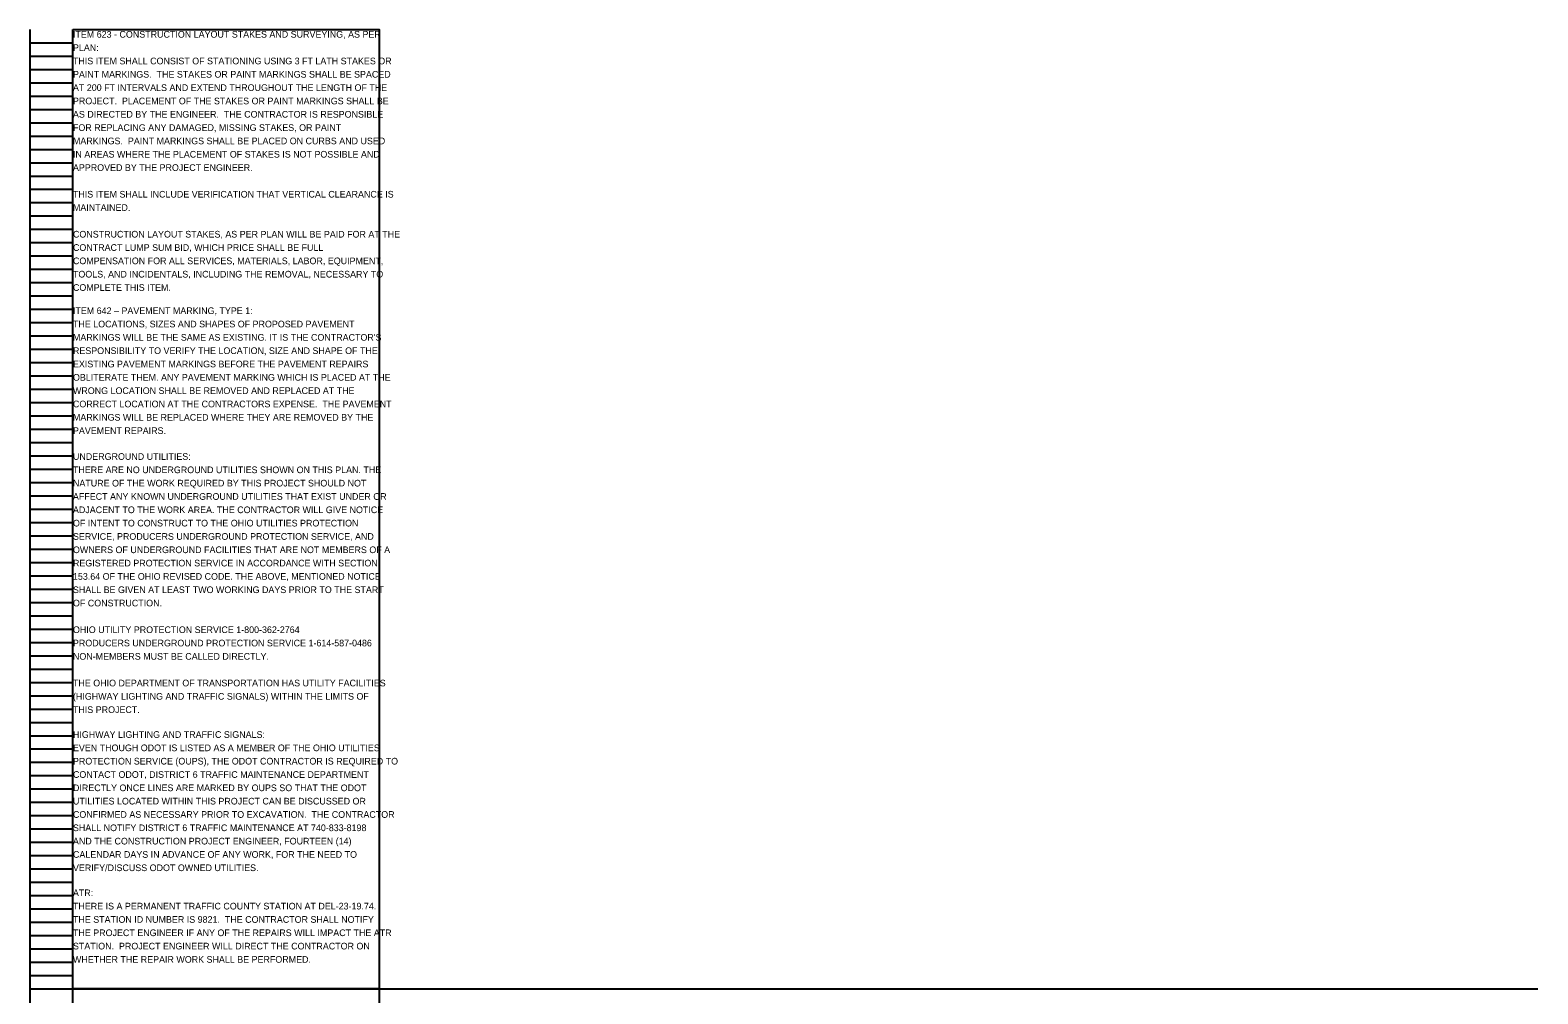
# Model space of a CAD drawing. Extents: x 16463 to 16495, y 5662 to 5823.
# Drawn here: x 16463.05 to 16494.74, y 5742.73 to 5762.98 of the extents above; entities that cross this region are included whole.
import ezdxf

# ---------------------------------------------------------------- set-up
doc = ezdxf.new("R2010")
doc.units = 0
for name, color, linetype in [('Default', 7, 'Continuous'), ('SC_Scratch1', 7, 'Continuous'), ('SH_Data', 7, 'Continuous')]:
    doc.layers.add(name, color=color, linetype=linetype)

msp = doc.modelspace()

# ---------------------------------------------------------------- linework, layer by layer
at = {"layer": 'SC_Scratch1'}
msp.add_line((16470.389, 5742.832), (16494.742, 5742.832), dxfattribs=at)
for points in [[(16463.949, 5762.992), (16470.389, 5762.992), (16470.389, 5742.832), (16463.949, 5742.832)], [(16463.949, 5742.832), (16470.389, 5742.832), (16470.389, 5722.672), (16463.949, 5722.672)]]:
    msp.add_lwpolyline(points, close=True, dxfattribs=at)
at = {"layer": 'SH_Data'}
for p, q in [((16463.049, 5742.832), (16463.049, 5762.992)), ((16463.949, 5742.832), (16463.949, 5762.992)), ((16463.049, 5762.712), (16463.949, 5762.712)), ((16463.049, 5762.432), (16463.949, 5762.432)), ((16463.049, 5762.152), (16463.949, 5762.152)), ((16463.049, 5761.872), (16463.949, 5761.872)), ((16463.049, 5761.592), (16463.949, 5761.592)), ((16463.049, 5761.312), (16463.949, 5761.312)), ((16463.049, 5761.032), (16463.949, 5761.032)), ((16463.049, 5760.752), (16463.949, 5760.752)), ((16463.049, 5760.472), (16463.949, 5760.472)), ((16463.049, 5760.192), (16463.949, 5760.192)), ((16463.049, 5759.912), (16463.949, 5759.912)), ((16463.049, 5759.632), (16463.949, 5759.632)), ((16463.049, 5759.352), (16463.949, 5759.352)), ((16463.049, 5759.072), (16463.949, 5759.072)), ((16463.049, 5758.792), (16463.949, 5758.792)), ((16463.049, 5758.512), (16463.949, 5758.512)), ((16463.049, 5758.232), (16463.949, 5758.232)), ((16463.049, 5757.952), (16463.949, 5757.952)), ((16463.049, 5757.672), (16463.949, 5757.672)), ((16463.049, 5757.392), (16463.949, 5757.392)), ((16463.049, 5757.112), (16463.949, 5757.112)), ((16463.049, 5756.832), (16463.949, 5756.832)), ((16463.049, 5756.552), (16463.949, 5756.552)), ((16463.049, 5756.272), (16463.949, 5756.272)), ((16463.049, 5755.992), (16463.949, 5755.992)), ((16463.049, 5755.712), (16463.949, 5755.712)), ((16463.049, 5755.432), (16463.949, 5755.432)), ((16463.049, 5755.152), (16463.949, 5755.152)), ((16463.049, 5754.872), (16463.949, 5754.872)), ((16463.049, 5754.592), (16463.949, 5754.592)), ((16463.049, 5754.312), (16463.949, 5754.312)), ((16463.049, 5754.032), (16463.949, 5754.032)), ((16463.049, 5753.752), (16463.949, 5753.752)), ((16463.049, 5753.472), (16463.949, 5753.472)), ((16463.049, 5753.192), (16463.949, 5753.192)), ((16463.049, 5752.912), (16463.949, 5752.912)), ((16463.049, 5752.632), (16463.949, 5752.632)), ((16463.049, 5752.352), (16463.949, 5752.352)), ((16463.049, 5752.072), (16463.949, 5752.072)), ((16463.049, 5751.792), (16463.949, 5751.792)), ((16463.049, 5751.512), (16463.949, 5751.512)), ((16463.049, 5751.232), (16463.949, 5751.232)), ((16463.049, 5750.952), (16463.949, 5750.952)), ((16463.049, 5750.672), (16463.949, 5750.672)), ((16463.049, 5750.392), (16463.949, 5750.392)), ((16463.049, 5750.112), (16463.949, 5750.112)), ((16463.049, 5749.832), (16463.949, 5749.832)), ((16463.049, 5749.552), (16463.949, 5749.552)), ((16463.049, 5749.272), (16463.949, 5749.272)), ((16463.049, 5748.992), (16463.949, 5748.992)), ((16463.049, 5748.712), (16463.949, 5748.712)), ((16463.049, 5748.432), (16463.949, 5748.432)), ((16463.049, 5748.152), (16463.949, 5748.152)), ((16463.049, 5747.872), (16463.949, 5747.872)), ((16463.049, 5747.592), (16463.949, 5747.592)), ((16463.049, 5747.312), (16463.949, 5747.312)), ((16463.049, 5747.032), (16463.949, 5747.032)), ((16463.049, 5746.752), (16463.949, 5746.752)), ((16463.049, 5746.472), (16463.949, 5746.472)), ((16463.049, 5746.192), (16463.949, 5746.192)), ((16463.049, 5745.912), (16463.949, 5745.912)), ((16463.049, 5745.632), (16463.949, 5745.632)), ((16463.049, 5745.352), (16463.949, 5745.352)), ((16463.049, 5745.072), (16463.949, 5745.072)), ((16463.049, 5744.792), (16463.949, 5744.792)), ((16463.049, 5744.512), (16463.949, 5744.512)), ((16463.049, 5744.232), (16463.949, 5744.232)), ((16463.049, 5743.952), (16463.949, 5743.952)), ((16463.049, 5743.672), (16463.949, 5743.672)), ((16463.049, 5743.392), (16463.949, 5743.392)), ((16463.049, 5743.112), (16463.949, 5743.112)), ((16463.049, 5722.672), (16463.049, 5742.832)), ((16463.049, 5742.832), (16463.949, 5742.832)), ((16463.049, 5742.832), (16463.949, 5742.832)), ((16463.949, 5722.672), (16463.949, 5742.832))]:
    msp.add_line(p, q, dxfattribs=at)

# ---------------------------------------------------------------- texts
at = {"layer": 'Default'}
for s, p in [('ITEM 623 - CONSTRUCTION LAYOUT STAKES AND SURVEYING, AS PER ', (16463.949, 5762.819)), ('PLAN:', (16463.949, 5762.539)), ('THIS ITEM SHALL CONSIST OF STATIONING USING 3 FT LATH STAKES OR ', (16463.949, 5762.259)), ('PAINT MARKINGS.  THE STAKES OR PAINT MARKINGS SHALL BE SPACED ', (16463.949, 5761.979)), ('AT 200 FT INTERVALS AND EXTEND THROUGHOUT THE LENGTH OF THE ', (16463.949, 5761.699)), ('PROJECT.  PLACEMENT OF THE STAKES OR PAINT MARKINGS SHALL BE ', (16463.949, 5761.419)), ('AS DIRECTED BY THE ENGINEER.  THE CONTRACTOR IS RESPONSIBLE ', (16463.949, 5761.139)), ('FOR REPLACING ANY DAMAGED, MISSING STAKES, OR PAINT ', (16463.949, 5760.859)), ('MARKINGS.  PAINT MARKINGS SHALL BE PLACED ON CURBS AND USED ', (16463.949, 5760.579)), ('IN AREAS WHERE THE PLACEMENT OF STAKES IS NOT POSSIBLE AND ', (16463.949, 5760.299)), ('APPROVED BY THE PROJECT ENGINEER.', (16463.949, 5760.019)), ('THIS ITEM SHALL INCLUDE VERIFICATION THAT VERTICAL CLEARANCE IS ', (16463.949, 5759.459)), ('MAINTAINED.', (16463.949, 5759.179)), ('CONSTRUCTION LAYOUT STAKES, AS PER PLAN WILL BE PAID FOR AT THE ', (16463.949, 5758.619)), ('CONTRACT LUMP SUM BID, WHICH PRICE SHALL BE FULL ', (16463.949, 5758.339)), ('COMPENSATION FOR ALL SERVICES, MATERIALS, LABOR, EQUIPMENT, ', (16463.949, 5758.059)), ('TOOLS, AND INCIDENTALS, INCLUDING THE REMOVAL, NECESSARY TO ', (16463.949, 5757.779)), ('COMPLETE THIS ITEM.', (16463.949, 5757.499)), ('ITEM 642 – PAVEMENT MARKING, TYPE 1:', (16463.949, 5757.011)), ('THE LOCATIONS, SIZES AND SHAPES OF PROPOSED PAVEMENT ', (16463.949, 5756.731)), ("MARKINGS WILL BE THE SAME AS EXISTING. IT IS THE CONTRACTOR'S ", (16463.949, 5756.451)), ('RESPONSIBILITY TO VERIFY THE LOCATION, SIZE AND SHAPE OF THE ', (16463.949, 5756.171)), ('EXISTING PAVEMENT MARKINGS BEFORE THE PAVEMENT REPAIRS ', (16463.949, 5755.891)), ('OBLITERATE THEM. ANY PAVEMENT MARKING WHICH IS PLACED AT THE ', (16463.949, 5755.611)), ('WRONG LOCATION SHALL BE REMOVED AND REPLACED AT THE ', (16463.949, 5755.331)), ('CORRECT LOCATION AT THE CONTRACTORS EXPENSE.  THE PAVEMENT ', (16463.949, 5755.051)), ('MARKINGS WILL BE REPLACED WHERE THEY ARE REMOVED BY THE ', (16463.949, 5754.771)), ('PAVEMENT REPAIRS.', (16463.949, 5754.491)), ('UNDERGROUND UTILITIES:', (16463.949, 5753.948)), ('THERE ARE NO UNDERGROUND UTILITIES SHOWN ON THIS PLAN. THE ', (16463.949, 5753.668)), ('NATURE OF THE WORK REQUIRED BY THIS PROJECT SHOULD NOT ', (16463.949, 5753.388)), ('AFFECT ANY KNOWN UNDERGROUND UTILITIES THAT EXIST UNDER OR ', (16463.949, 5753.108)), ('ADJACENT TO THE WORK AREA. THE CONTRACTOR WILL GIVE NOTICE ', (16463.949, 5752.828)), ('OF INTENT TO CONSTRUCT TO THE OHIO UTILITIES PROTECTION ', (16463.949, 5752.548)), ('SERVICE, PRODUCERS UNDERGROUND PROTECTION SERVICE, AND ', (16463.949, 5752.268)), ('OWNERS OF UNDERGROUND FACILITIES THAT ARE NOT MEMBERS OF A ', (16463.949, 5751.988)), ('REGISTERED PROTECTION SERVICE IN ACCORDANCE WITH SECTION ', (16463.949, 5751.708)), ('153.64 OF THE OHIO REVISED CODE. THE ABOVE, MENTIONED NOTICE ', (16463.949, 5751.428)), ('SHALL BE GIVEN AT LEAST TWO WORKING DAYS PRIOR TO THE START ', (16463.949, 5751.148)), ('OF CONSTRUCTION.', (16463.949, 5750.868)), ('OHIO UTILITY PROTECTION SERVICE 1-800-362-2764', (16463.949, 5750.308)), ('PRODUCERS UNDERGROUND PROTECTION SERVICE 1-614-587-0486', (16463.949, 5750.028)), ('NON-MEMBERS MUST BE CALLED DIRECTLY.', (16463.949, 5749.748)), ('THE OHIO DEPARTMENT OF TRANSPORTATION HAS UTILITY FACILITIES ', (16463.949, 5749.188)), ('(HIGHWAY LIGHTING AND TRAFFIC SIGNALS) WITHIN THE LIMITS OF ', (16463.949, 5748.908)), ('THIS PROJECT.', (16463.949, 5748.628)), ('HIGHWAY LIGHTING AND TRAFFIC SIGNALS:', (16463.949, 5748.106)), ('EVEN THOUGH ODOT IS LISTED AS A MEMBER OF THE OHIO UTILITIES ', (16463.949, 5747.826)), ('CONTACT ODOT, DISTRICT 6 TRAFFIC MAINTENANCE DEPARTMENT ', (16463.949, 5747.266)), ('PROTECTION SERVICE (OUPS), THE ODOT CONTRACTOR IS REQUIRED TO ', (16463.949, 5747.546)), ('DIRECTLY ONCE LINES ARE MARKED BY OUPS SO THAT THE ODOT ', (16463.949, 5746.986)), ('UTILITIES LOCATED WITHIN THIS PROJECT CAN BE DISCUSSED OR ', (16463.949, 5746.706)), ('CONFIRMED AS NECESSARY PRIOR TO EXCAVATION.  THE CONTRACTOR ', (16463.949, 5746.426)), ('SHALL NOTIFY DISTRICT 6 TRAFFIC MAINTENANCE AT 740-833-8198 ', (16463.949, 5746.146)), ('AND THE CONSTRUCTION PROJECT ENGINEER, FOURTEEN (14) ', (16463.949, 5745.866)), ('CALENDAR DAYS IN ADVANCE OF ANY WORK, FOR THE NEED TO ', (16463.949, 5745.586)), ('VERIFY/DISCUSS ODOT OWNED UTILITIES.', (16463.949, 5745.306)), ('ATR:', (16463.949, 5744.78)), ('THERE IS A PERMANENT TRAFFIC COUNTY STATION AT DEL-23-19.74.  ', (16463.949, 5744.5)), ('THE STATION ID NUMBER IS 9821.  THE CONTRACTOR SHALL NOTIFY ', (16463.949, 5744.22)), ('THE PROJECT ENGINEER IF ANY OF THE REPAIRS WILL IMPACT THE ATR ', (16463.949, 5743.94)), ('STATION.  PROJECT ENGINEER WILL DIRECT THE CONTRACTOR ON ', (16463.949, 5743.66)), ('WHETHER THE REPAIR WORK SHALL BE PERFORMED.', (16463.949, 5743.38))]:
    msp.add_text(s, height=0.14, dxfattribs=at).set_placement(p)

doc.saveas('drawing.dxf')
